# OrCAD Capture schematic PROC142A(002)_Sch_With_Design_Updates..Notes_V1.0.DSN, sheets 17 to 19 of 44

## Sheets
17 16. DDR4 INTERFACE: size C; title: DDR4 Interface
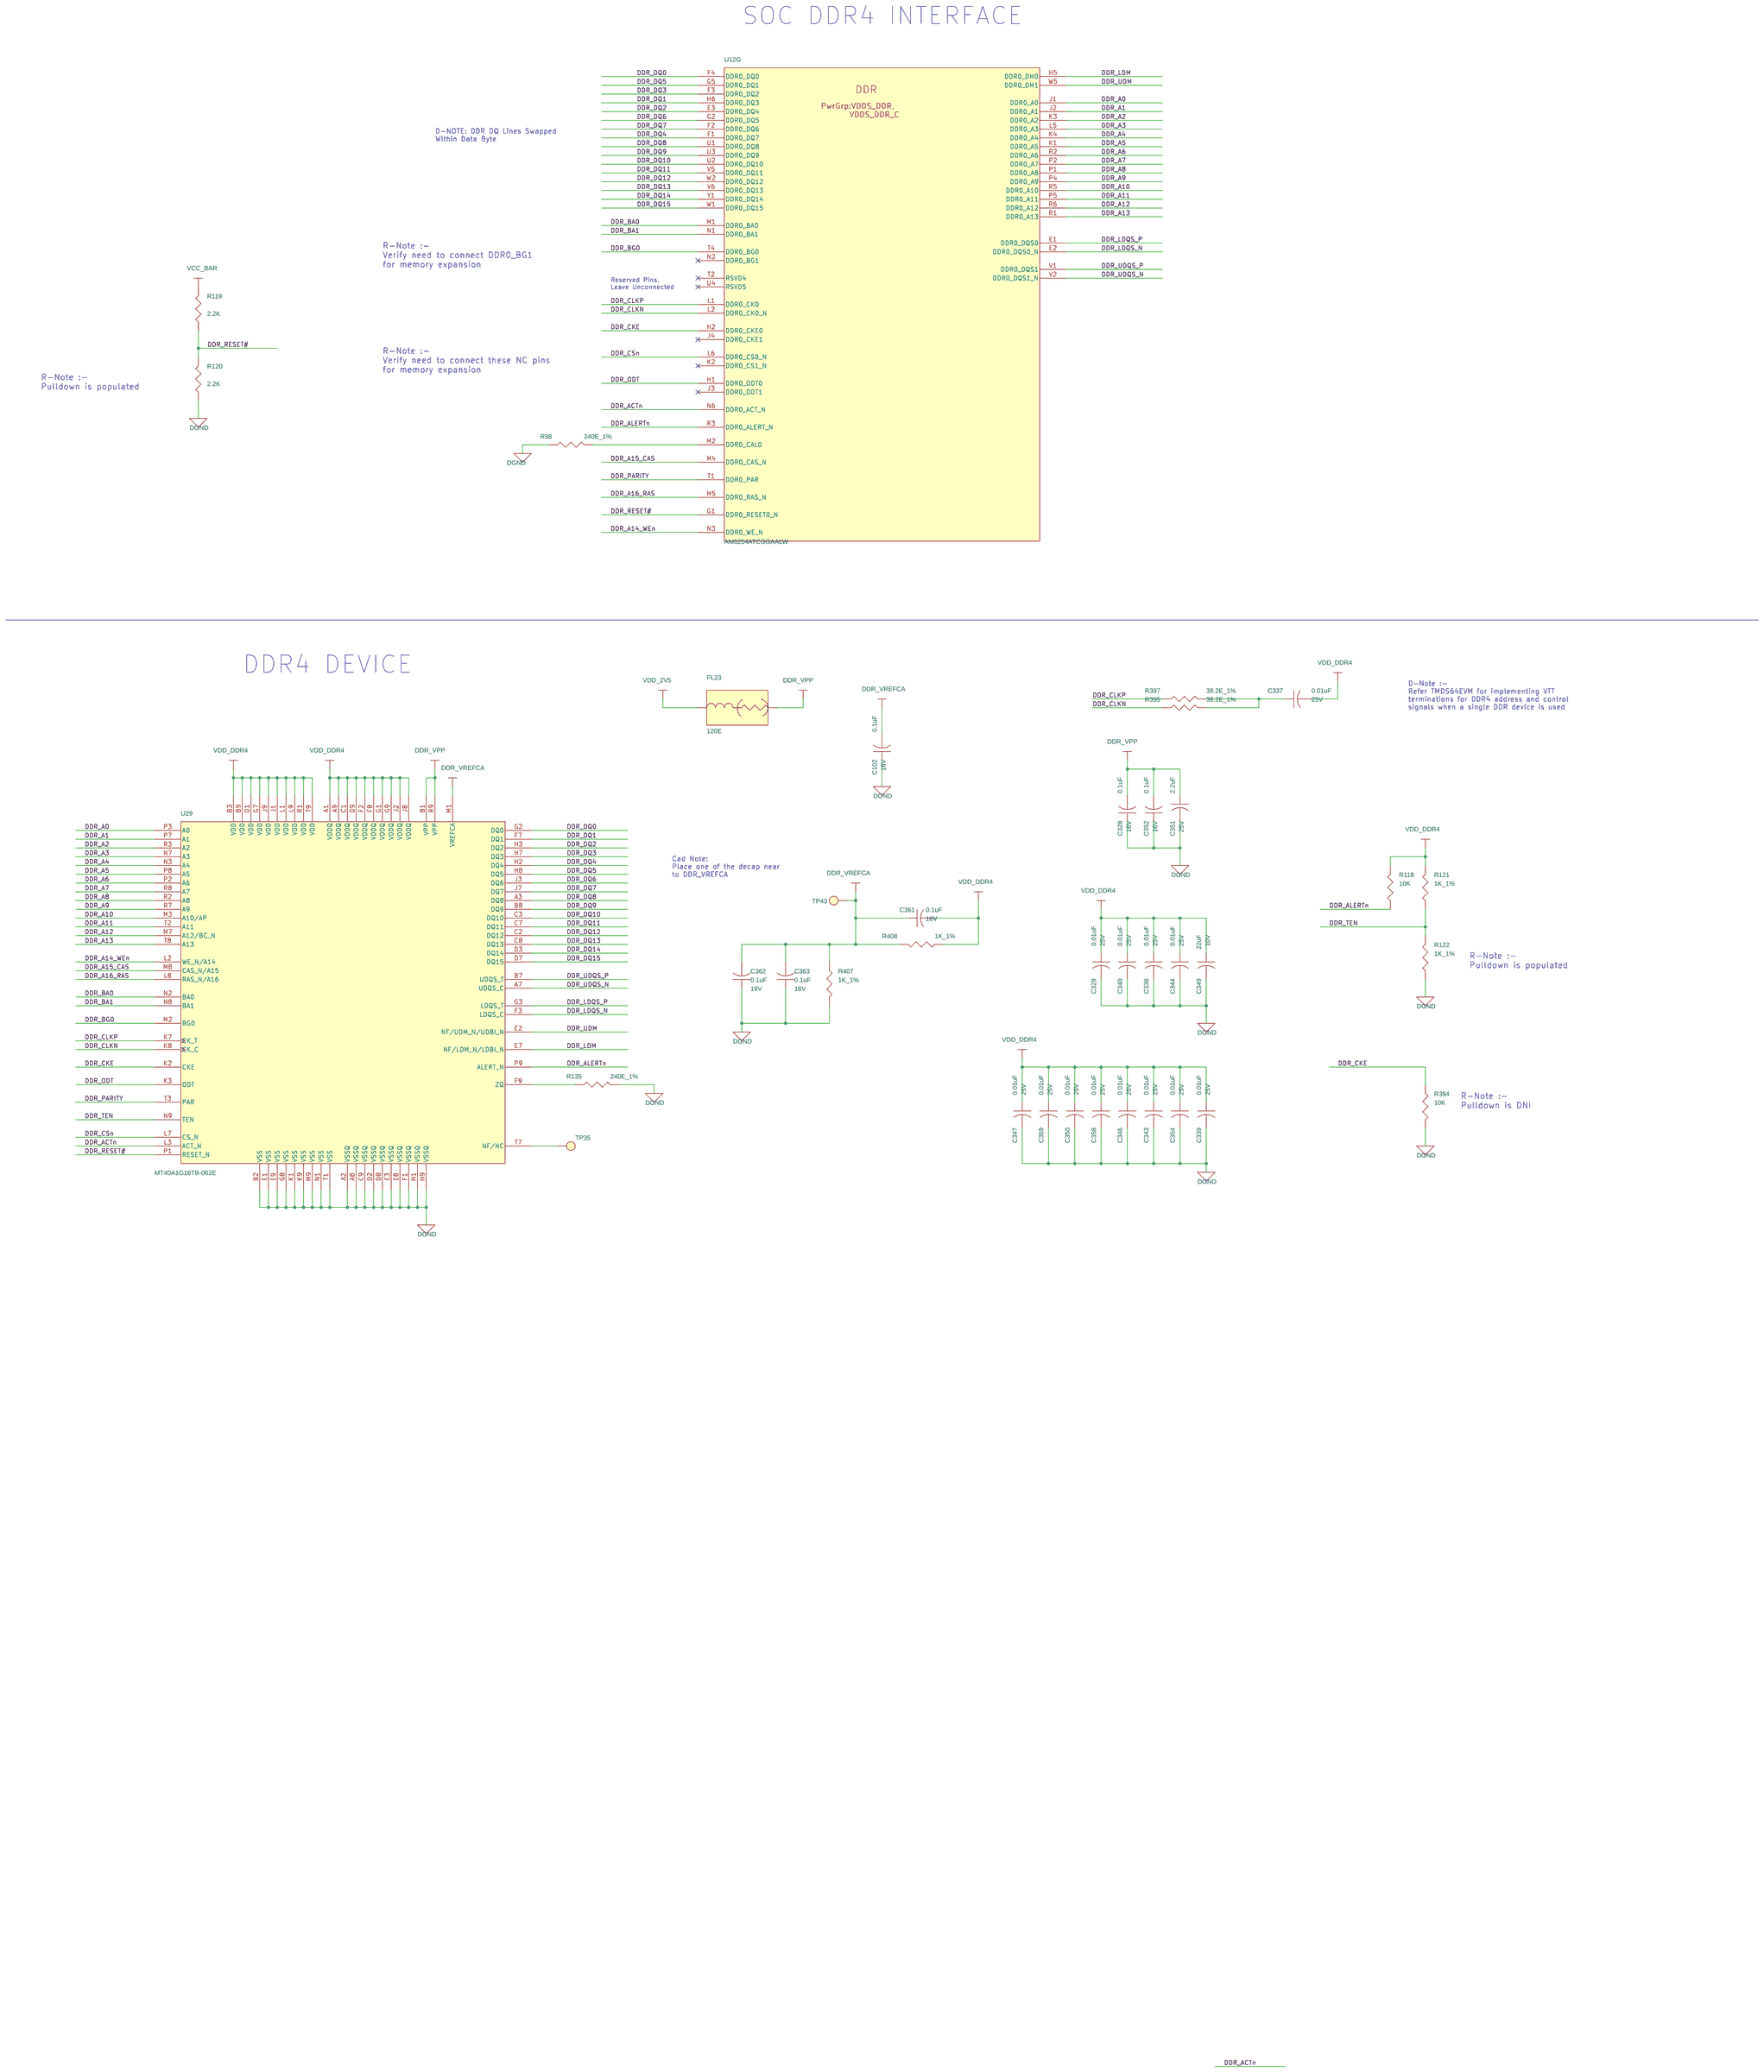
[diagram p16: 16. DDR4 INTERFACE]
18 17. M.2 INTERFACE: size C; title: M.2 CONNECTOR
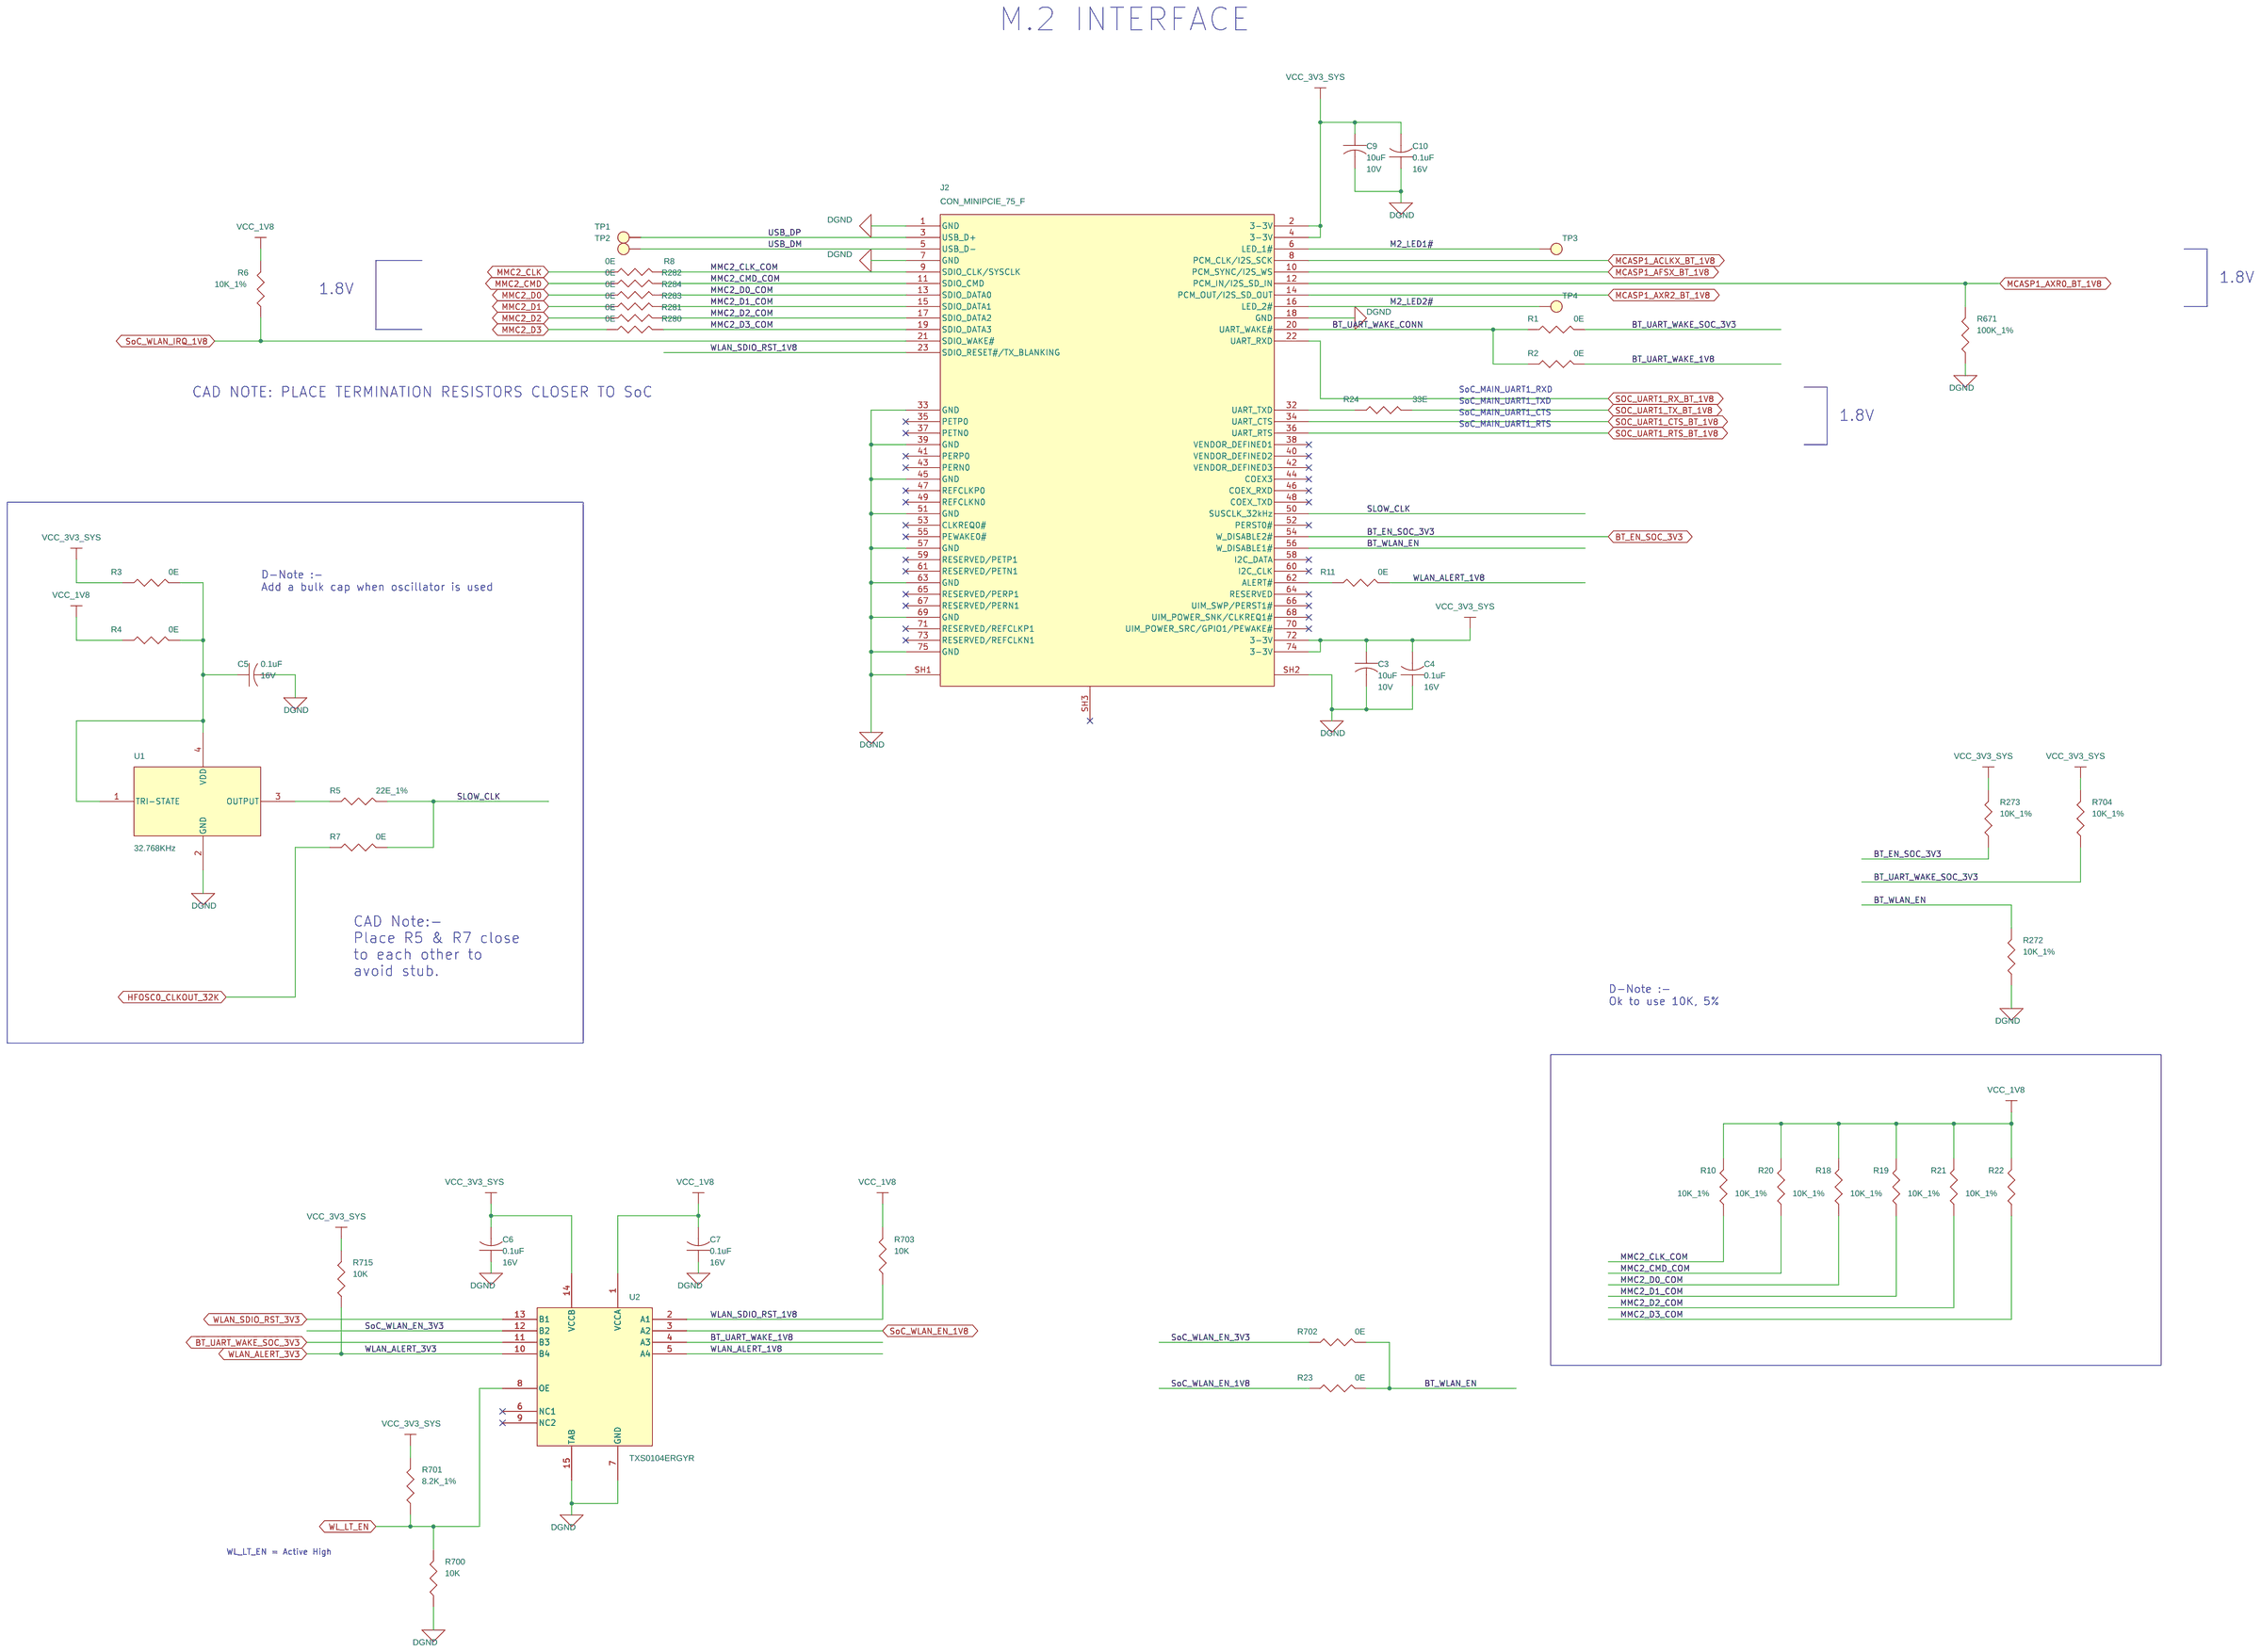
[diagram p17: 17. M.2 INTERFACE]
19 18. eMMC FLASH: size C; title: eMMC FLASH INTERFACE
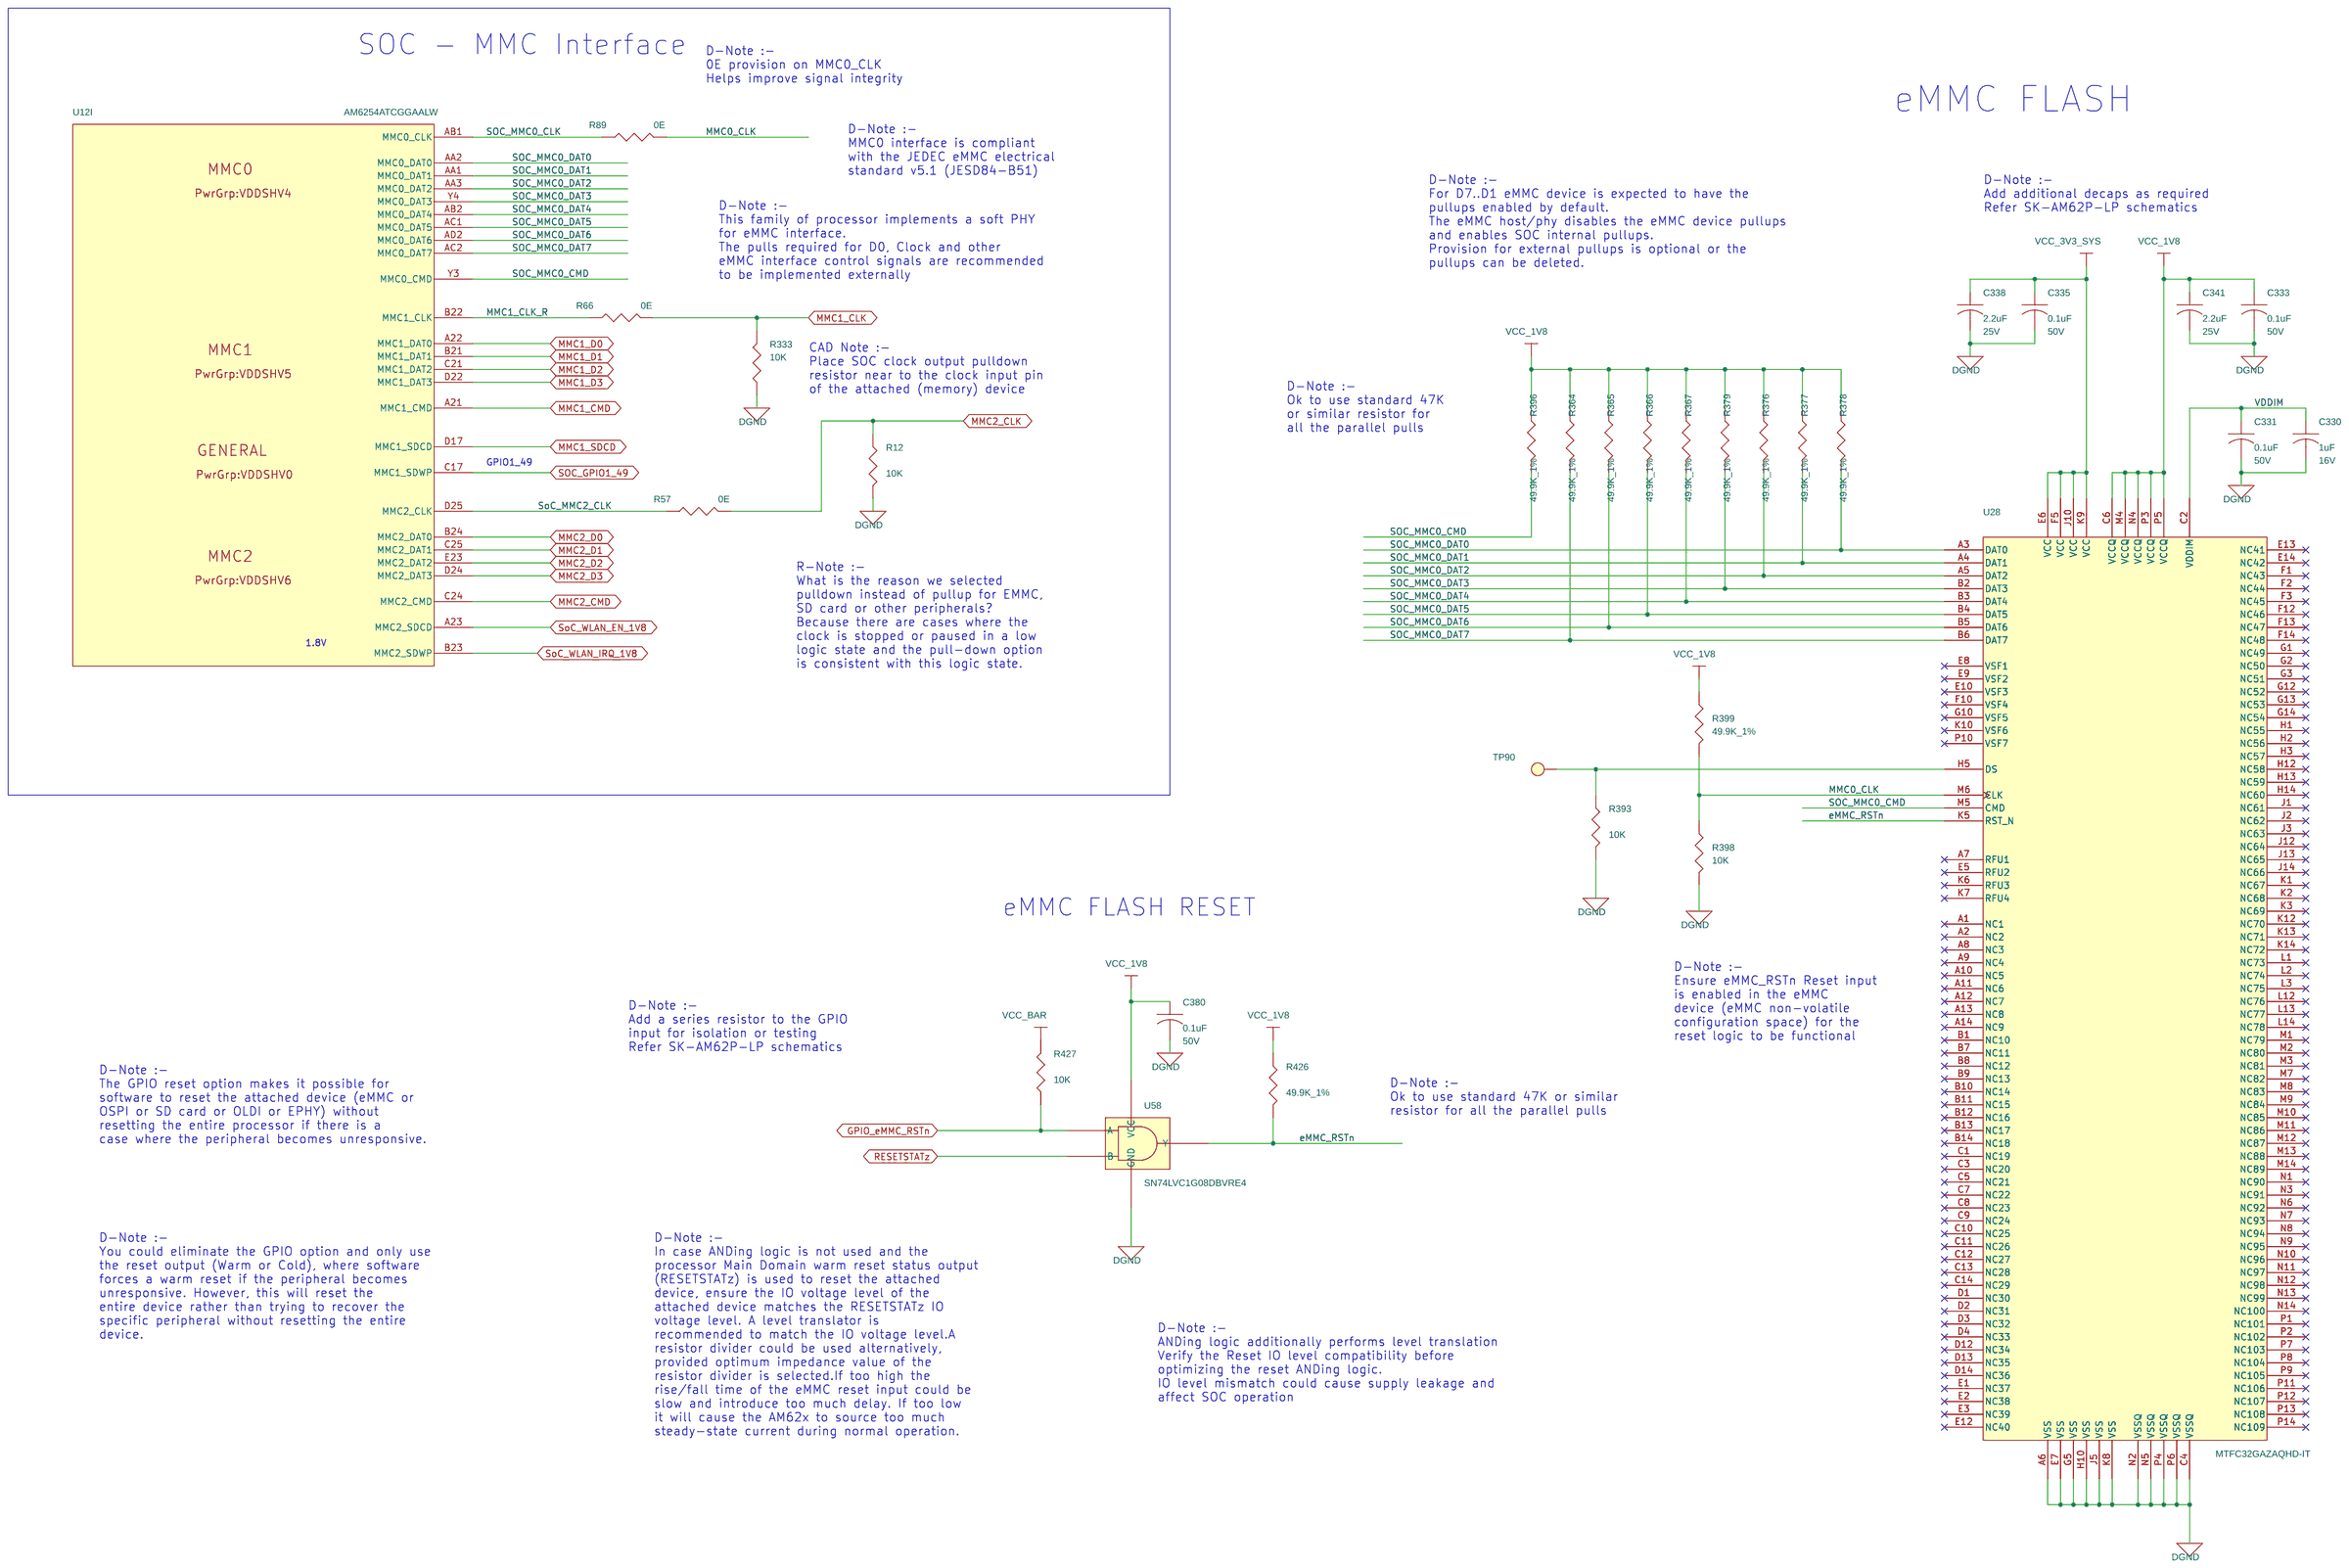
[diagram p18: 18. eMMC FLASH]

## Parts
sheet 16. DDR4 INTERFACE
C102  0.1uF  [CAP0201_0-5]
C328  0.1uF  [CAP0201_0-5]
C329  0.01uF  [CAP0201_0-5]
C336  0.01uF  [CAP0201_0-5]
C337  0.01uF  [CAP0201_0-5]
C339  0.01uF  [CAP0201_0-5]
C340  0.01uF  [CAP0201_0-5]
C343  0.01uF  [CAP0201_0-5]
C344  0.01uF  [CAP0201_0-5]
C346  0.01uF  [CAP0201_0-5]
C347  0.01uF  [CAP0201_0-5]
C349  22uF  [CAP0603_1]
C350  0.01uF  [CAP0201_0-5]
C351  2.2uF  [CAP0402_0-75]
C352  0.1uF  [CAP0201_0-5]
C354  0.01uF  [CAP0201_0-5]
C358  0.01uF  [CAP0201_0-5]
C359  0.01uF  [CAP0201_0-5]
C361  0.1uF  [CAP0201_0-5]
C362  0.1uF  [CAP0201_0-5]
C363  0.1uF  [CAP0201_0-5]
FL23  120E  [EMIFIL_BLM15A_0402_0-6]
R98  240E_1%  [RES0402_0-5]
R118  10K  [RES0201_0-5]
R119  2.2K  [RES0201_0-5]
R120  2.2K  [RES0402_0-5]
R121  1K_1%  [RES0402_0-5]
R122  1K_1%  [RES0402_0-5]
R135  240E_1%  [RES0402_0-5]
R394  10K  [RES0201_0-5]
R395  39.2E_1%  [RES0402_0-5]
R397  39.2E_1%  [RES0402_0-5]
R407  1K_1%  [RES0201_0-5]
R408  1K_1%  [RES0201_0-5]
TP35  TP20_SMD  [TP20_SMD]
TP43  TP20_SMD  [TP20_SMD]
U29  MT40A1G16TB-062E  [FBGA96_31-49_300X520_1-2]
sheet 17. M.2 INTERFACE
C3  10uF  [CAP0402_0-75]
C4  0.1uF  [CAP0201_0-5]
C5  0.1uF  [CAP0201_0-5]
C6  0.1uF  [CAP0201_0-5]
C7  0.1uF  [CAP0201_0-5]
C9  10uF  [CAP0402_0-75]
C10  0.1uF  [CAP0201_0-5]
J2  CON_MINIPCIE_75_F  [CON_MINIPCI75_2199119-4_S_R_S_3-2_2230]
R1  0E  [RES0201_0-5]
R2  0E  [RES0201_0-5]
R3  0E  [RES0201_0-5]
R4  0E  [RES0201_0-5]
R5  22E_1%  [RES0201_0-5]
R6  10K_1%  [RES0201_0-5]
R7  0E  [RES0201_0-5]
R8  0E  [RES0402_0-5]
R10  10K_1%  [RES0201_0-5]
R11  0E  [RES0201_0-5]
R18  10K_1%  [RES0201_0-5]
R19  10K_1%  [RES0201_0-5]
R20  10K_1%  [RES0201_0-5]
R21  10K_1%  [RES0201_0-5]
R22  10K_1%  [RES0201_0-5]
R23  0E  [RES0201_0-5]
R24  33E  [RES0201_0-5]
R272  10K_1%  [RES0201_0-5]
R273  10K_1%  [RES0201_0-5]
R280  0E  [RES0402_0-5]
R281  0E  [RES0402_0-5]
R282  0E  [RES0402_0-5]
R283  0E  [RES0402_0-5]
R284  0E  [RES0402_0-5]
R671  100K_1%  [RES0402_0-5]
R700  10K  [RES0201_0-5]
R701  8.2K_1%  [RES0201_0-5]
R702  0E  [RES0201_0-5]
R703  10K  [RES0201_0-5]
R704  10K_1%  [RES0201_0-5]
R715  10K  [RES0201_0-5]
TP1  TP20_SMD  [TP20_SMD]
TP2  TP20_SMD  [TP20_SMD]
TP3  TP20_SMD  [TP20_SMD]
TP4  TP20_SMD  [TP20_SMD]
U1  32.768KHz  [OSC4_ASDK_105X85_SMD]
U2  TXS0104ERGYR  [QFN14_19-68_145X145]
sheet 18. eMMC FLASH
C330  1uF  [CAP0201_0-5]
C331  0.1uF  [CAP0402_0-75]
C333  0.1uF  [CAP0402_0-75]
C335  0.1uF  [CAP0402_0-75]
C338  2.2uF  [CAP0402_0-75]
C341  2.2uF  [CAP0402_0-75]
C380  0.1uF  [CAP0402_0-75]
R12  10K  [RES0201_0-5]
R57  0E  [RES0201_0-5]
R66  0E  [RES0201_0-5]
R89  0E  [RES0201_0-5]
R333  10K  [RES0201_0-5]
R364  49.9K_1%  [RES0201_0-5]
R365  49.9K_1%  [RES0201_0-5]
R366  49.9K_1%  [RES0201_0-5]
R367  49.9K_1%  [RES0201_0-5]
R376  49.9K_1%  [RES0201_0-5]
R377  49.9K_1%  [RES0201_0-5]
R378  49.9K_1%  [RES0201_0-5]
R379  49.9K_1%  [RES0201_0-5]
R393  10K  [RES0201_0-5]
R396  49.9K_1%  [RES0201_0-5]
R398  10K  [RES0201_0-5]
R399  49.9K_1%  [RES0402_0-5]
R426  49.9K_1%  [RES0402_0-5]
R427  10K  [RES0201_0-5]
TP90  TP20_SMD  [TP20_SMD]
U28  MTFC32GAZAQHD-IT  [VFBGA153_19-68_460X520_0-9]
U58  SN74LVC1G08DBVRE4  [SOT23-5]
sheet 42. OSCILLATOR
U12  AM6254ATCGGAALW  [BGA425_19-68_510X510_0-7]  (sections A,B,C,D,E,F,G,H,I,J,K,L,M,N,O,P,Q,R)

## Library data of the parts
C102 C328 C352 = CAP: CAP CERAMIC 0.1uF 16V 10% X5R 0201; Chkd/date: MANIRAJA/230118; Crtd /date: MANIRAJA/230118; Custom_Duty: 15%; Customs_HS_Code: 85322990; Distributor_name: DIGIKEY; Distributor_part_number: 490-14305-1-ND; Footprint Path: Y:\MIS_DATABASE\Library\ALTIUM_TOOL\PCB_FOOTPRINTS\Altium_Footprint_Lib.PcbLib; Height: 0.33MM; Library Path: Y:\MIS_DATABASE\Library\ALTIUM_TOOL\SCHEMATICS_PARTS\MS_DISCRETE_Library.schlib; Mfr_name: MURATA; Mfr_part_number: GRM033R61C104KE14D; Mistral Part No: 120009030072-R; Package: 0201; Part_type: CAPACITORS\CERAMIC; Project: TI_MAXIE_CPB; RoHS: RoHS; Temperature: -55°C+85°C; Tolerance: 10%; Voltage: 16V; Wattage: NA; Weight: 0.33mg; Datasheet: Y:\MIS_DATABASE\DATASHEETS\CAPACITORS\GRM033R61C104KE14.PDF
C329 C336 C337 C339 C340 C343 C344 C346 C347 C350 C354 C358 C359 = CAP: CAP CERAMIC 0.01uF 25V 10% X5R 0201; Chkd/date: MANIRAJA/230118; Crtd /date: MANIRAJA/230118; Custom_Duty: 15%; Customs_HS_Code: 85322990; Distributor_name: DIGIKEY; Distributor_part_number: GRM033R61E103KA12J-ND; Footprint Path: Y:\MIS_DATABASE\Library\ALTIUM_TOOL\PCB_FOOTPRINTS\Altium_Footprint_Lib.PcbLib; Height: 0.33MM; Library Path: Y:\MIS_DATABASE\Library\ALTIUM_TOOL\SCHEMATICS_PARTS\MS_DISCRETE_Library.schlib; Mfr_name: MURATA; Mfr_part_number: GRM033R61E103KA12J; Mistral Part No: 120018010007-R; Package: 0201; Part_type: CAPACITORS\CERAMIC; Project: TI_MAXIE_CPB; RoHS: RoHS; Temperature: -55°C+85°C; Tolerance: 10%; Voltage: 25V; Wattage: NA; Weight: 0.33mg; Datasheet: Y:\MIS_DATABASE\DATASHEETS\CAPACITORS\GRM033R61E103KA12.PDF
C349 = CAP: CAP CERAMIC 22uF 10V 20% X5R 0603; Chkd/date: MANIRAJA/230118; Crtd /date: MANIRAJA/230118; Custom_Duty: 15%; Customs_HS_Code: 85322990; Distributor_name: DIGIKEY; Distributor_part_number: 490-10476-1-ND; Footprint Path: Y:\MIS_DATABASE\Library\ALTIUM_TOOL\PCB_FOOTPRINTS\Altium_Footprint_Lib.PcbLib; Height: 1.00MM; Library Path: Y:\MIS_DATABASE\Library\ALTIUM_TOOL\SCHEMATICS_PARTS\MS_DISCRETE_Library.schlib; Mfr_name: MURATA; Mfr_part_number: GRM188R61A226ME15D; Mistral Part No: 120014100009-R; Package: 0603; Part_type: CAPACITORS\CERAMIC; Project: TI_MAXIE_CPB; RoHS: RoHS; Temperature: -55°C+85°C; Tolerance: 20%; Voltage: 10V; Wattage: NA; Weight: 6.3mg; Datasheet: Y:\MIS_DATABASE\DATASHEETS\CAPACITORS\GRM188R61A226ME15.PDF
C338 C341 C351 = CAP: CAP CERAMIC 2.2uF 25V 10% X5R 0402; Chkd/date: ALVY/010721; Crtd /date: MANIRAJA/010721; Custom_Duty: 15%; Customs_HS_Code: 85322990; Distributor_name: DIGIKEY; Distributor_part_number: 490-12703-1-ND; Footprint Path: Y:\MIS_DATABASE\Library\ALTIUM_TOOL\PCB_FOOTPRINTS\Altium_Footprint_Lib.PcbLib; Height: 0.70MM; Library Path: Y:\MIS_DATABASE\Library\ALTIUM_TOOL\SCHEMATICS_PARTS\MS_DISCRETE_Library.schlib; Mfr_name: MURATA; Mfr_part_number: GRM155R61E225KE11D; Mistral Part No: 120015120001-R; Package: 0402; Part_type: CAPACITORS\CERAMIC; Project: TI_AM263X_CC; RoHS: RoHS; Temperature: -55°C+85°C; Tolerance: 10%; Voltage: 25V; Wattage: NA; Weight: 1.5mg; Datasheet: Y:\MIS_DATABASE\DATASHEETS\CAPACITORS\GRM155R61E225KE11.PDF
C4-C7 C10 C361-C363 = CAP: CAP CERAMIC 0.1uF 16V 10% X5R 0201; Alt_Mfr_name: YAGEO AMERICA; Alt_Mfr_part_number: CC0402KRX5R8BB104; Chkd/date: MANIRAJA/230118; Crtd /date: MANIRAJA/230118; Custom_Duty: 15%; Customs_HS_Code: 85322990; Distributor_name: DIGIKEY; Distributor_part_number: 490-14305-1-ND; Footprint Path: Y:\MIS_DATABASE\Library\ALTIUM_TOOL\PCB_FOOTPRINTS\Altium_Footprint_Lib.PcbLib; Height: 0.33MM; Library Path: Y:\MIS_DATABASE\Library\ALTIUM_TOOL\SCHEMATICS_PARTS\MS_DISCRETE_Library.schlib; Mfr_name: MURATA; Mfr_part_number: GRM033R61C104KE14D; Mistral Part No: 120009030072-R; Package: 0201; Part_type: CAPACITORS\CERAMIC; Project: TI_MAXIE_CPB; RoHS: RoHS; Temperature: -55°C+85°C; Tolerance: 10%; Voltage: 16V; Wattage: NA; Weight: 0.33mg; Datasheet: Y:\MIS_DATABASE\DATASHEETS\CAPACITORS\GRM033R61C104KE14.PDF
FL23 = EMIFILTER_IND: IND FERRITE BEAD CHIP 120E 2A 0402; Chkd/date: NAVEED/241114; Crtd /date: USMAN/170613; Custom_Duty: 24%; Customs_HS_Code: 85369090; Distributor_name: DIGIKEY; Distributor_part_number: 490-9656-1-ND; Footprint Path: Y:\MIS_DATABASE\Library\ALTIUM_TOOL\PCB_FOOTPRINTS\Altium_Footprint_Lib.PcbLib; Height: 0.55MM; Library Path: Y:\MIS_DATABASE\Library\ALTIUM_TOOL\SCHEMATICS_PARTS\MS_FILTER_Library.schlib; Mfr_name: MURATA; Mfr_part_number: BLM15PX121SN1D; Mistral Part No: 130013060022-R; Package: 0402; Part_type: INDUCTOR; Project: GEN_3-8; RoHS: RoHS; Temperature: -55°C+125°C; Tolerance: 25%; Voltage: NA; Wattage: NA; Weight: 1mg; Datasheet: Y:\MIS_DATABASE\DATASHEETS\DISCRETES\INDUCTORS\BLM15-SN1-SER.PDF
R98 R135 = RESISTOR: RES 240E 1/10W 1% 0402; Chkd/date: MAZHAR/150611; Crtd /date: BAVISH/020611; Custom_Duty: 15%; Customs_HS_Code: 85332119; Distributor_name: DIGIKEY; Distributor_part_number: P240LCT-ND; Footprint Path: Y:\MIS_DATABASE\Library\ALTIUM_TOOL\PCB_FOOTPRINTS\Altium_Footprint_Lib.PcbLib; Height: 0.40MM; Library Path: Y:\MIS_DATABASE\Library\ALTIUM_TOOL\SCHEMATICS_PARTS\MS_DISCRETE_Library.schlib; Mfr_name: PANASONIC-ECG; Mfr_part_number: ERJ-2RKF2400X; Mistral Part No: 110011060017-R; Package: 0402; Part_type: RESISTORS\FIXED; Project: AM4515_EVM_LCD; RoHS: RoHS; Temperature: -55°C+155°C; Tolerance: 1%; Voltage: NA; Wattage: 1/10W; Weight: 0.8mg; Datasheet: Y:\MIS_DATABASE\DATASHEETS\RESISTORS\PAN-ERJSER_NOV17.PDF
R12 R118 R333 R393 R394 R398 R427 R700 R703 R715 = RESISTOR: RES 10K 1/20W 5% 0201; Chkd/date: MANIRAJA/050517; Crtd /date: MANIRAJA/050517; Custom_Duty: 15%; Customs_HS_Code: 85332119; Distributor_name: DIGIKEY; Distributor_part_number: 311-10KNCT-ND; Footprint Path: Y:\MIS_DATABASE\Library\ALTIUM_TOOL\PCB_FOOTPRINTS\Altium_Footprint_Lib.PcbLib; Height: 0.26MM; Library Path: Y:\MIS_DATABASE\Library\ALTIUM_TOOL\SCHEMATICS_PARTS\MS_DISCRETE_Library.schlib; Mfr_name: YAGEO AMERICA; Mfr_part_number: RC0201JR-0710KL; Mistral Part No: 110010070051-R; Package: 0201; Part_type: RESISTORS\FIXED; Project: GOLDEN-I LITE; RoHS: RoHS; Temperature: -55°C+125°C; Tolerance: 5%; Voltage: NA; Wattage: 1/20W; Weight: 0.17mg; Datasheet: Y:\MIS_DATABASE\DATASHEETS\RESISTORS\RCXXXXL-SER_MAR18.PDF
R119 = RESISTOR: RES 2.2K 1/20W 5% 0201; Chkd/date: VASANTHA/010117; Crtd /date: MAZHAR/010605; Custom_Duty: 15%; Customs_HS_Code: 85332119; Distributor_name: DIGIKEY; Distributor_part_number: P2.2KAGCT-ND; Footprint Path: Y:\MIS_DATABASE\Library\ALTIUM_TOOL\PCB_FOOTPRINTS\Altium_Footprint_Lib.PcbLib; Height: 0.26MM; Library Path: Y:\MIS_DATABASE\Library\ALTIUM_TOOL\SCHEMATICS_PARTS\MS_DISCRETE_Library.schlib; Mfr_name: PANASONIC-ECG; Mfr_part_number: ERJ-1GEJ222C; Mistral Part No: 110009030427-R; Package: 0201; Part_type: RESISTORS\FIXED; Project: G4SLIM; RoHS: RoHS; Temperature: -55°C+125°C; Tolerance: 5%; Voltage: NA; Wattage: 1/20W; Weight: 0.15mg; Datasheet: Y:\MIS_DATABASE\DATASHEETS\RESISTORS\PAN-ERJXGE-FEB06.PDF
R120 = RESISTOR: RES 2.2K 1/16W 5% 0402; Chkd/date: VASANTHA/061216; Crtd /date: BAVISH/021210; Custom_Duty: 15%; Customs_HS_Code: 85332119; Distributor_name: DIGIKEY; Distributor_part_number: 311-2.2KJRCT-ND; Footprint Path: Y:\MIS_DATABASE\Library\ALTIUM_TOOL\PCB_FOOTPRINTS\Altium_Footprint_Lib.PcbLib; Height: 0.40MM; Library Path: Y:\MIS_DATABASE\Library\ALTIUM_TOOL\SCHEMATICS_PARTS\MS_DISCRETE_Library.schlib; Mfr_name: YAGEO AMERICA; Mfr_part_number: RC0402JR-072K2L; Mistral Part No: 110010120018-R; Package: 0402; Part_type: RESISTORS\FIXED; Project: TE4; RoHS: RoHS; Temperature: -55°C+155°C; Tolerance: 5%; Voltage: NA; Wattage: 1/16W; Weight: 0.65mg; Datasheet: Y:\MIS_DATABASE\DATASHEETS\RESISTORS\RCXXXXL-SER_MAR18.PDF
R121 R122 = RESISTOR: RES 1K 1/10W 1% 0402; Chkd/date: VASANTHA/281216; Crtd /date: MAZHAR/150506; Custom_Duty: 15%; Customs_HS_Code: 85332119; Distributor_name: DIGIKEY; Distributor_part_number: P1.00KLCT-ND; Footprint Path: Y:\MIS_DATABASE\Library\ALTIUM_TOOL\PCB_FOOTPRINTS\Altium_Footprint_Lib.PcbLib; Height: 0.40MM; Library Path: Y:\MIS_DATABASE\Library\ALTIUM_TOOL\SCHEMATICS_PARTS\MS_DISCRETE_Library.schlib; Mfr_name: PANASONIC-ECG; Mfr_part_number: ERJ-2RKF1001X; Mistral Part No: 110009030411-R; Package: 0402; Part_type: RESISTORS\FIXED; Project: VOCERA; RoHS: RoHS; Temperature: -55°C+155°C; Tolerance: 1%; Voltage: NA; Wattage: 1/10W; Weight: 0.8mg; Datasheet: Y:\MIS_DATABASE\DATASHEETS\RESISTORS\PAN-ERJSER_NOV17.PDF
R395 R397 = RESISTOR: RES 39.2E 1/16W 1% 0402; Chkd/date: RAGESH/210411; Crtd /date: MAZHAR/210411; Custom_Duty: 15%; Customs_HS_Code: 85332119; Distributor_name: DIGIKEY; Distributor_part_number: RMCF0402FT39R2CT-ND; Footprint Path: Y:\MIS_DATABASE\Library\ALTIUM_TOOL\PCB_FOOTPRINTS\Altium_Footprint_Lib.PcbLib; Height: 0.40MM; Library Path: Y:\MIS_DATABASE\Library\ALTIUM_TOOL\SCHEMATICS_PARTS\MS_DISCRETE_Library.schlib; Mfr_name: STACKPOLE ELECTRONICS; Mfr_part_number: RMCF0402FT39R2; Mistral Part No: 110011040030-R; Package: 0402; Part_type: RESISTORS\FIXED; Project: AOD_POD-BASECARD; RoHS: RoHS; Temperature: -55°C+155°C; Tolerance: 1%; Voltage: NA; Wattage: 1/16W; Weight: 0.57mg; Datasheet: Y:\MIS_DATABASE\DATASHEETS\RESISTORS\RMCF-SER_JUL18.PDF
R407 R408 = RESISTOR: RES 1K 1/20W 1% 0201; Chkd/date: PRAVEEN/110822; Crtd /date: PRAVEEN/110822; Custom_Duty: 15%; Customs_HS_Code: 85332119; Distributor_name: DIGIKEY; Distributor_part_number: P122413CT-ND; Footprint Path: Y:\MIS_DATABASE\Library\ALTIUM_TOOL\PCB_FOOTPRINTS\Altium_Footprint_Lib.PcbLib; Height: 0.26MM; Library Path: Y:\MIS_DATABASE\Library\ALTIUM_TOOL\SCHEMATICS_PARTS\MS_DISCRETE_Library.schlib; Mfr_name: PANASONIC-ECG; Mfr_part_number: ERJ-1GNF1001C; Mistral Part No: 110022080039-R; Package: 0201; Part_type: RESISTORS\FIXED; Project: QCS6490 SOM_BRD; RoHS: RoHS; Temperature: -55°C+125°C; Tolerance: 1%; Voltage: NA; Wattage: 1/20W; Weight: 0.15mg; Datasheet: Y:\MIS_DATABASE\DATASHEETS\RESISTORS\PAN-ERJSER_NOV17.PDF
TP1-TP4 TP35 TP43 TP90 = TESTPOINT: TESTPOINT CIR 20 SMD; Chkd/date: SHREESHAIL/171006; Crtd /date: MAZHAR/171006; Custom_Duty: NA; Customs_HS_Code: NA; Distributor_name: NA; Distributor_part_number: NA; Footprint Path: Y:\MIS_DATABASE\Library\ALTIUM_TOOL\PCB_FOOTPRINTS\Altium_Footprint_Lib.PcbLib; Height: NA; Library Path: Y:\MIS_DATABASE\Library\ALTIUM_TOOL\SCHEMATICS_PARTS\MS_DISCRETE_Library.schlib; MECHANICAL 3D STEP FILE: NA; Mfr_name: LOCAL; Mistral Part No: NA; Package: SMD; Project: BT MODULE_CSRBC04; RoHS: NA; Temperature: NA; Tolerance: NA; Voltage: NA; Wattage: NA; Weight: NA; Datasheet: NA
U29 = MT40A512M16LY_FBGA96: IC 16Gb DDR4 SDRAM FBGA96; Chkd/date: PRAVEEN/031122; Crtd /date: PRAVEEN/031122; Custom_Duty: 15%; Customs_HS_Code: 85423100; Distributor_name: DIGIKEY; Distributor_part_number: 557-MT40A1G16TB-062EIT:F-ND; Footprint Path: Y:\MIS_DATABASE\Library\ALTIUM_TOOL\PCB_FOOTPRINTS\Altium_Footprint_Lib.PcbLib; Height: 1.20MM; Library Path: Y:\MIS_DATABASE\Library\ALTIUM_TOOL\SCHEMATICS_PARTS\MS_MISCMEMORY_Library.schlib; Mfr_name: MICRON; Mfr_part_number: MT40A1G16TB-062E IT:F; Mistral Part No: 141022110006-R; Package: FBGA96; Part_type: ICS\DIGITAL\MEMORY; Project: AM64x_SK_BRD; RoHS: RoHS; Temperature: -40°C+95°C; Tolerance: NA; Voltage: NA; Wattage: NA; Weight: NA; Datasheet: Y:\MIS_DATABASE\DATASHEETS\ICS\MEMORY\MT40A-SER.PDF
C3 C9 = CAP: CAP CERAMIC 10uF 10V 20% X5R 0402; Chkd/date: MANIRAJA/300520; Crtd /date: ALVY/260520; Custom_Duty: 15%; Customs_HS_Code: 85322990; Distributor_name: DIGIKEY; Distributor_part_number: 490-GRM155R61A106ME11DTR-ND; Footprint Path: Y:\MIS_DATABASE\Library\ALTIUM_TOOL\PCB_FOOTPRINTS\Altium_Footprint_Lib.PcbLib; Height: 0.55MM; Library Path: Y:\MIS_DATABASE\Library\ALTIUM_TOOL\SCHEMATICS_PARTS\MS_DISCRETE_Library.schlib; Mfr_name: MURATA; Mfr_part_number: GRM155R61A106ME11D; Mistral Part No: 120013110019-R; Package: 0402; Part_type: CAPACITORS\CERAMIC; Project: QCS610_NANOSOM; RoHS: RoHS; Temperature: -55°C+85°C; Tolerance: 20%; Voltage: 10V; Wattage: NA; Weight: 3.1mg; Datasheet: Y:\MIS_DATABASE\DATASHEETS\CAPACITORS\MURATA-GXX-SER_NOV17.PDF
J2 = CON_PCI_75_2199119-4_2230: CON MINIPCI 75POS 0.50MM PITCH FEMALE RT SMD; Chkd/date: ALVY/300521; Crtd /date: ALVY/300521; Custom_Duty: 24%; Customs_HS_Code: 85369090; Distributor_name: DIGIKEY; Distributor_part_number: A115900CT-ND; Footprint Path: Y:\MIS_DATABASE\Library\ALTIUM_TOOL\PCB_FOOTPRINTS\Altium_Footprint_Lib.PcbLib; Height: 3.20MM; Library Path: Y:\MIS_DATABASE\Library\ALTIUM_TOOL\SCHEMATICS_PARTS\MS_CONNECTOR_Library.schlib; Mfr_name: TE CONNECTIVITY; Mfr_part_number: 2199119-4_2230; Mistral Part No: 150021030016-R; Package: SMD; Part_type: CONNECTOR\PCI; Project: VOLTA_CHARGER V5; RoHS: RoHS; Temperature: -40°C+80°C; Tolerance: NA; Voltage: NA; Wattage: NA; Weight: 506mg; Datasheet: Y:\MIS_DATABASE\DATASHEETS\CONNECTORS\2199119.PDF
R1-R4 R7 R11 R23 R702 = RESISTOR: RES 0E 1/20W 5% 0201; Chkd/date: NAVEED/301214; Crtd /date: MUDDU/120710; Custom_Duty: 15%; Customs_HS_Code: 85332119; Distributor_name: DIGIKEY; Distributor_part_number: 311-0.0NCT-ND; Footprint Path: Y:\MIS_DATABASE\Library\ALTIUM_TOOL\PCB_FOOTPRINTS\Altium_Footprint_Lib.PcbLib; Height: 0.26MM; Library Path: Y:\MIS_DATABASE\Library\ALTIUM_TOOL\SCHEMATICS_PARTS\MS_DISCRETE_Library.schlib; Mfr_name: YAGEO AMERICA; Mfr_part_number: RC0201JR-070RL; Mistral Part No: 110010070067-R; Package: 0201; Part_type: RESISTORS\FIXED; Project: PB_BUGBASE; RoHS: RoHS; Temperature: -55°C+125°C; Tolerance: 5%; Voltage: NA; Wattage: 1/20W; Weight: 0.17mg; Datasheet: Y:\MIS_DATABASE\DATASHEETS\RESISTORS\RCXXXXL-SER_MAR18.PDF
R5 = RESISTOR: RES 22E 1/20W 1% 0201; Chkd/date: MAZHAR/140709; Crtd /date: MAZHAR/220807; Custom_Duty: 15%; Customs_HS_Code: 85332119; Distributor_name: DIGIKEY; Distributor_part_number: P22.0ABCT-ND; Footprint Path: Y:\MIS_DATABASE\Library\ALTIUM_TOOL\PCB_FOOTPRINTS\Altium_Footprint_Lib.PcbLib; Height: 0.26MM; Library Path: Y:\MIS_DATABASE\Library\ALTIUM_TOOL\SCHEMATICS_PARTS\MS_DISCRETE_Library.schlib; Mfr_name: PANASONIC-ECG; Mfr_part_number: ERJ-1GEF22R0C; Mistral Part No: 110009030522-R; Package: 0201; Part_type: RESISTORS\FIXED; Project: V8TS; RoHS: RoHS; Temperature: -55°C+125°C; Tolerance: 1%; Voltage: NA; Wattage: 1/20W; Weight: 0.15mg; Datasheet: Y:\MIS_DATABASE\DATASHEETS\RESISTORS\PAN-ERJSER_NOV17.PDF
R6 R10 R18-R22 R272 R273 R704 = RESISTOR: RES 10K 1/20W 1% 0201; Chkd/date: VASANTHA/270117; Crtd /date: MANIRAJA/270117; Custom_Duty: 15%; Customs_HS_Code: 85332119; Distributor_name: DIGIKEY; Distributor_part_number: 311-10.0KMCT-ND; Footprint Path: Y:\MIS_DATABASE\Library\ALTIUM_TOOL\PCB_FOOTPRINTS\Altium_Footprint_Lib.PcbLib; Height: 0.26MM; Library Path: Y:\MIS_DATABASE\Library\ALTIUM_TOOL\SCHEMATICS_PARTS\MS_DISCRETE_Library.schlib; Mfr_name: YAGEO AMERICA; Mfr_part_number: RC0201FR-0710KL; Mistral Part No: 110011040018-R; Package: 0201; Part_type: RESISTORS\FIXED; Project: GOLDEN-I LITE; RoHS: RoHS; Temperature: -55°C+125°C; Tolerance: 1%; Voltage: NA; Wattage: 1/20W; Weight: 0.17mg; Datasheet: Y:\MIS_DATABASE\DATASHEETS\RESISTORS\RCXXXXL-SER_MAR18.PDF
R8 R280-R284 = RESISTOR: RES 0E 1/16W JUMPER 0402; Chkd/date: VASANTHA/201216; Crtd /date: MUDDU/190810; Custom_Duty: 15%; Customs_HS_Code: 85332119; Distributor_name: DIGIKEY; Distributor_part_number: 541-0.0JCT-ND; Footprint Path: Y:\MIS_DATABASE\Library\ALTIUM_TOOL\PCB_FOOTPRINTS\Altium_Footprint_Lib.PcbLib; Height: 0.40MM; Library Path: Y:\MIS_DATABASE\Library\ALTIUM_TOOL\SCHEMATICS_PARTS\MS_DISCRETE_Library.schlib; Mfr_name: VISHAY; Mfr_part_number: CRCW04020000Z0ED; Mistral Part No: 110010080019-R; Package: 0402; Part_type: RESISTORS\FIXED; Project: PB_BUGBASE; RoHS: RoHS; Temperature: -55°C+155°C; Tolerance: NA; Voltage: NA; Wattage: 1/16W; Weight: 0.65mg; Datasheet: Y:\MIS_DATABASE\DATASHEETS\RESISTORS\CRCW0603.PDF
R24 = RESISTOR: RES 33E 1/20W 5% 0201; Chkd/date: VASANTHA/061216; Crtd /date: MAZHAR/170505; Custom_Duty: 15%; Customs_HS_Code: 85332119; Distributor_name: DIGIKEY; Distributor_part_number: P33AGCT-ND; Footprint Path: Y:\MIS_DATABASE\Library\ALTIUM_TOOL\PCB_FOOTPRINTS\Altium_Footprint_Lib.PcbLib; Height: 0.26MM; Library Path: Y:\MIS_DATABASE\Library\ALTIUM_TOOL\SCHEMATICS_PARTS\MS_DISCRETE_Library.schlib; Mfr_name: PANASONIC-ECG; Mfr_part_number: ERJ-1GEJ330C; Mistral Part No: 110010070052-R; Package: 0201; Part_type: RESISTORS\FIXED; Project: G4SLIM; RoHS: RoHS; Temperature: -55°C+125°C; Tolerance: 5%; Voltage: NA; Wattage: 1/20W; Weight: 0.15mg; Datasheet: Y:\MIS_DATABASE\DATASHEETS\RESISTORS\PAN-ERJXGE-FEB06.PDF
R671 = RESISTOR: RES 100K 1/10W 1% 0402; Chkd/date: VASANTHA/201216; Crtd /date: MAZHAR/130306; Custom_Duty: 15%; Customs_HS_Code: 85332119; Distributor_name: DIGIKEY; Distributor_part_number: P100KLCT-ND; Footprint Path: Y:\MIS_DATABASE\Library\ALTIUM_TOOL\PCB_FOOTPRINTS\Altium_Footprint_Lib.PcbLib; Height: 0.40MM; Library Path: Y:\MIS_DATABASE\Library\ALTIUM_TOOL\SCHEMATICS_PARTS\MS_DISCRETE_Library.schlib; Mfr_name: PANASONIC-ECG; Mfr_part_number: ERJ-2RKF1003X; Mistral Part No: 110009030187-R; Package: 0402; Part_type: RESISTORS\FIXED; Project: J32; RoHS: RoHS; Temperature: -55°C+155°C; Tolerance: 1%; Voltage: NA; Wattage: 1/10W; Weight: 0.8mg; Datasheet: Y:\MIS_DATABASE\DATASHEETS\RESISTORS\PAN-ERJSER_NOV17.PDF
R701 = RESISTOR: RES 8.2K 1/20W 1% 0201; Chkd/date: SUHAS/230910; Crtd /date: MUDDU/060710; Custom_Duty: 15%; Customs_HS_Code: 85332119; Distributor_name: DIGIKEY; Distributor_part_number: 541-8.20KAABCT-ND; Footprint Path: Y:\MIS_DATABASE\Library\ALTIUM_TOOL\PCB_FOOTPRINTS\Altium_Footprint_Lib.PcbLib; Height: 0.28MM; Library Path: Y:\MIS_DATABASE\Library\ALTIUM_TOOL\SCHEMATICS_PARTS\MS_DISCRETE_Library.schlib; Mfr_name: VISHAY; Mfr_part_number: CRCW02018K20FKED; Mistral Part No: 110010070001-R; Package: 0201; Part_type: RESISTORS\FIXED; Project: PB_BUGBASE; RoHS: RoHS; Temperature: -55°C+155°C; Tolerance: 1%; Voltage: NA; Wattage: 1/20W; Weight: 0.17mg; Datasheet: Y:\MIS_DATABASE\DATASHEETS\RESISTORS\CRCW0201.PDF
U1 = OSC4_ASFL3: OSC 32.768KHz 1.8V SMD; Chkd/date: SUHAS/100710; Crtd /date: USMAN/020409; Custom_Duty: 24%; Customs_HS_Code: 85437099; Distributor_name: DIGIKEY; Distributor_part_number: 535-10003-1-ND; Height: 0.95MM; Mfr_name: ABRACON; Mfr_part_number: ASDK2-32.768KHZ-LRT; Mistral Part No: 130009031113-R; Package: SMD; Part_type: OSCILLATORS; Project: AXON; RoHS: RoHS; Temperature: -40°C+85°C; Voltage: 1.8V; Weight: NA; Datasheet: Y:\MIS_DATABASE\DATASHEETS\MISC\CRY_OSC\ASDK.PDF
U2 = TXS0104ERGYR_QFN14: IC 4-BIT BIDIRECTIONAL VOLTAGE-LEVEL TRANSLATOR QFN14; Chkd/date: SHREESHAIL/170108; Crtd /date: SHREESHAIL/170108; Custom_Duty: 15%; Customs_HS_Code: 85423100; Distributor_name: DIGIKEY; Distributor_part_number: 296-20698-1-ND; Height: 1.00MM; Mfr_name: TEXAS INSTRUMENTS; Mistral Part No: 141009030362-R; Package: QFN14; Part_type: ICS\INTERFACE; Project: HS100RD; RoHS: Sb/ Br FREE; Datasheet: Y:\MIS_DATABASE\DATASHEETS\ICS\INTERFACE\TXS0104E.PDF
C330 = CAP: CAP CERAMIC 1uF 16V 20% X5R 0201; Chkd/date: MANIRAJA/300520; Crtd /date: ALVY/260520; Custom_Duty: 15%; Customs_HS_Code: 85322990; Distributor_name: DIGIKEY; Distributor_part_number: 490-18654-1-ND; Footprint Path: Y:\MIS_DATABASE\Library\ALTIUM_TOOL\PCB_FOOTPRINTS\Altium_Footprint_Lib.PcbLib; Height: 0.39MM; Library Path: Y:\MIS_DATABASE\Library\ALTIUM_TOOL\SCHEMATICS_PARTS\MS_DISCRETE_Library.schlib; Mfr_name: MURATA; Mfr_part_number: GRM033R61C105ME15D; Mistral Part No: 120018090038-R; Package: 0201; Part_type: CAPACITORS\CERAMIC; Project: QCS610_NANOSOM; RoHS: RoHS; Temperature: -55°C+85°C; Tolerance: 20%; Voltage: 16V; Wattage: NA; Weight: 0.33mg; Datasheet: Y:\MIS_DATABASE\DATASHEETS\CAPACITORS\GRM033R61C105ME15.PDF
C331 C333 C335 C380 = CAP: CAP CERAMIC 0.1uF 50V 10% X7R 0402; Alt_Mfr_name: YAGEO AMERICA; Alt_Mfr_part_number: CC0402KRX5R8BB104; Chkd/date: MANIRAJA/261020; Crtd /date: ALVY/211020; Custom_Duty: 15%; Customs_HS_Code: 85322990; Distributor_name: DIGIKEY; Distributor_part_number: 490-10700-1-ND; Footprint Path: Y:\MIS_DATABASE\Library\ALTIUM_TOOL\PCB_FOOTPRINTS\Altium_Footprint_Lib.PcbLib; Height: 0.55MM; Library Path: Y:\MIS_DATABASE\Library\ALTIUM_TOOL\SCHEMATICS_PARTS\MS_DISCRETE_Library.schlib; Mfr_name: MURATA; Mfr_part_number: GRM155R71H104KE14D; Mistral Part No: 120011100014-R; Package: 0402; Part_type: CAPACITORS\CERAMIC; Project: J7_CP; RoHS: RoHS; Temperature: -55°C+125°C; Tolerance: 10%; Voltage: 50V; Wattage: NA; Weight: 3.1mg; Datasheet: Y:\MIS_DATABASE\DATASHEETS\CAPACITORS\GRM155R71H104KE14.PDF
R57 R66 = RESISTOR: RES 0E 1/20W 5% 0201; Chkd/date: NAVEED/301214; Crtd /date: MUDDU/120710; Custom_Duty: 15%; Customs_HS_Code: 85332119; Distributor_name: DIGIKEY; Distributor_part_number: 311-0.0NCT-ND; Footprint Path: Y:\MIS_DATABASE\Library\ALTIUM_TOOL\PCB_FOOTPRINTS\Altium_Footprint_Lib.PcbLib; Height: 0.26MM; Library Path: Y:\MIS_DATABASE\Library\ALTIUM_TOOL\SCHEMATICS_PARTS\MS_DISCRETE_Library.schlib; Mfr_name: YAGEO AMERICA; Mfr_part_number: RC0201JR-070RL; Mistral Part No: 110010070067-R; Package: 0201; Part_type: RESISTORS\FIXED; Project: PB_BUGBASE; RoHS: RoHS; SIGNAL_MODEL: RESISTOR_RES0201_0-5_0E_0E; Temperature: -55°C+125°C; Tolerance: 5%; Voltage: NA; Wattage: 1/20W; Weight: 0.17mg; Datasheet: Y:\MIS_DATABASE\DATASHEETS\RESISTORS\RCXXXXL-SER_MAR18.PDF
R89 = RESISTOR: RES 0E 1/20W 5% 0201; Chkd/date: NAVEED/301214; Crtd /date: MUDDU/120710; Custom_Duty: 15%; Customs_HS_Code: 85332119; Distributor_name: DIGIKEY; Distributor_part_number: 311-0.0NCT-ND; Footprint Path: Y:\MIS_DATABASE\Library\ALTIUM_TOOL\PCB_FOOTPRINTS\Altium_Footprint_Lib.PcbLib; Height: 0.26MM; Library Path: Y:\MIS_DATABASE\Library\ALTIUM_TOOL\SCHEMATICS_PARTS\MS_DISCRETE_Library.schlib; Mfr_name: YAGEO AMERICA; Mfr_part_number: RC0201JR-070RL; Mistral Part No: 110010070067-R; Package: 0201; Part_type: RESISTORS\FIXED; Project: PB_BUGBASE; RoHS: RoHS; SIGNAL_MODEL: RESISTOR_RES0201_0-5_22E_1%_22E_1%; Temperature: -55°C+125°C; Tolerance: 5%; Voltage: NA; Wattage: 1/20W; Weight: 0.17mg; Datasheet: Y:\MIS_DATABASE\DATASHEETS\RESISTORS\RCXXXXL-SER_MAR18.PDF
R364-R367 R376-R379 R396 = RESISTOR: RES 49.9K 1/20W 1% 0201; Chkd/date: MAZHAR/140108; Crtd /date: USMAN/140108; Cust_part_number: 4700-80185E; Custom_Duty: 15%; Customs_HS_Code: 85332119; Distributor_name: DIGIKEY; Distributor_part_number: P49.9KABCT-ND; Footprint Path: Y:\MIS_DATABASE\Library\ALTIUM_TOOL\PCB_FOOTPRINTS\Altium_Footprint_Lib.PcbLib; Height: 0.26MM; Library Path: Y:\MIS_DATABASE\Library\ALTIUM_TOOL\SCHEMATICS_PARTS\MS_DISCRETE_Library.schlib; Mfr_name: PANASONIC-ECG; Mfr_part_number: ERJ-1GEF4992C; Mistral Part No: 110009030900-R; Package: 0201; Part_type: RESISTORS\FIXED; Project: SD_WATERLOO; RoHS: RoHS; Temperature: -55°C+125°C; Tolerance: 1%; Voltage: NA; Wattage: 1/20W; Weight: 0.15mg; Datasheet: Y:\MIS_DATABASE\DATASHEETS\RESISTORS\PAN-ERJSER_NOV17.PDF
R399 R426 = RESISTOR: RES 49.9K 1/16W 1% 0402; Chkd/date: MAZHAR/220709; Crtd /date: GEETHA/090606; Custom_Duty: 15%; Customs_HS_Code: 85332119; Distributor_name: DIGIKEY; Distributor_part_number: 311-49.9KLRCT-ND; Footprint Path: Y:\MIS_DATABASE\Library\ALTIUM_TOOL\PCB_FOOTPRINTS\Altium_Footprint_Lib.PcbLib; Height: 0.40MM; Library Path: Y:\MIS_DATABASE\Library\ALTIUM_TOOL\SCHEMATICS_PARTS\MS_DISCRETE_Library.schlib; Mfr_name: YAGEO AMERICA; Mfr_part_number: RC0402FR-0749K9L; Mistral Part No: 110009030902-R; Package: 0402; Part_type: RESISTORS\FIXED; Project: PNAV; RoHS: RoHS; Temperature: -55°C+155°C; Tolerance: 1%; Voltage: NA; Wattage: 1/16W; Weight: 0.65mg; Datasheet: Y:\MIS_DATABASE\DATASHEETS\RESISTORS\RCXXXXL-SER_MAR18.PDF
U28 = MTFC16GAPALBH_TFBGA153: IC 32GB e-MMC MEMORY VFBGA153; Chkd/date: PRAVEEN/010922; Crtd /date: PRAVEEN/010922; Custom_Duty: 15%; Customs_HS_Code: 85423100; Distributor_name: DIGIKEY; Distributor_part_number: 557-MTFC32GAZAQHD-IT-ND; Footprint Path: Y:\MIS_DATABASE\Library\ALTIUM_TOOL\PCB_FOOTPRINTS\Altium_Footprint_Lib.PcbLib; Height: 0.90MM; Library Path: Y:\MIS_DATABASE\Library\ALTIUM_TOOL\SCHEMATICS_PARTS\MS_MISCMEMORY_Library.schlib; Mfr_name: MICRON; Mistral Part No: 141122090001-R; Package: VFBGA153; Part_type: ICS\DIGITAL\MEMORY; Project: J7AHP_SK_BRD; RoHS: RoHS; Temperature: -40°C+95°C; Tolerance: NA; Voltage: NA; Wattage: NA; Weight: NA; Datasheet: Y:\MIS_DATABASE\DATASHEETS\ICS\MEMORY\MTFC64GAZAQHD-IT.PDF
U58 = SN74LVC1G08DBVRE4_SOT23-5: IC SINGLE 2-INPUT POSITIVE AND GATE SOT23-5; Chkd/date: SUHAS/221010; Crtd /date: USMAN/151008; Custom_Duty: 15%; Customs_HS_Code: 85423100; Distributor_name: DIGIKEY; Distributor_part_number: SN74LVC1G08DBVRE4-ND; Height: 1.45MM; Mfr_name: TEXAS INSTRUMENTS; Mistral Part No: 141009060026-R; Part_type: ICS\DIGITAL\GATES; Project: KHAN_MAIN; RoHS: Sb/ Br FREE; Temperature: -40°C+85°C; Datasheet: Y:\MIS_DATABASE\DATASHEETS\ICS\DIGITAL\GATES\SN74LVC1G08.PDF
U12 = AM62-EVM_BGA425: IC AM62 SoC MICROPROCESSOR BGA425; Chkd/date: ALVY/110621; Crtd /date: MANIRAJA/110621; Custom_Duty: 15%; Customs_HS_Code: 85423100; Distributor_name: NA; Distributor_part_number: NA; Footprint Path: Y:\MIS_DATABASE\Library\ALTIUM_TOOL\PCB_FOOTPRINTS\Altium_Footprint_Lib.PcbLib; Height: 0.65MM; Library Path: Y:\MIS_DATABASE\Library\ALTIUM_TOOL\SCHEMATICS_PARTS\MS_MICROPROCESSOR_Library.schlib; Mfr_name: TEXAS INSTRUMENTS; Mistral Part No: 141221060001; Package: BGA425; Part_type: ICS\DIGITAL\MICROPROCESSOR; Project: AM62_EVM_BRD; RoHS: NA; Temperature: NA; Tolerance: NA; Voltage: NA; Wattage: NA; Weight: NA; Datasheet: Y:\MIS_DATABASE\DATASHEETS\ICS\DIGITAL\MICROCONTROLLER\AM62-SoC_SVB.PDF

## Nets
DGND: C3.2 C4.1 C5.2 C6.1 C7.1 C9.2 C10.1 C102.1 C328.1 C329.2 C330.2 C331.2 C333.2 C335.2 C336.2 C338.2 C339.2 C340.2 C341.2 C343.2 C344.2 C346.2 C347.2 C349.2 C350.2 C351.2 C352.1 C354.2 C358.2 C359.2 C362.1 C363.1 C380.2 J2.1(GND) J2.7(GND) J2.18(GND) J2.33(GND) J2.39(GND) J2.45(GND) J2.51(GND) J2.57(GND) J2.63(GND) J2.69(GND) J2.75(GND) J2.SH1 J2.SH2 R12.2 R98.2 R120.1 R122.1 R135.2 R272.2 R333.2 R393.2 R394.2 R398.2 R407.2 R671.1 R700.1 U1.2(GND) U2.7(GND) U2.15(TAB) U28.A6(VSS) U28.C4(VSSQ) U28.E7(VSS) U28.G5(VSS) U28.H10(VSS) U28.J5(VSS) U28.K8(VSS) U28.N2(VSSQ) U28.N5(VSSQ) U28.P4(VSSQ) U28.P6(VSSQ) U29.A2(VSSQ) U29.A8(VSSQ) U29.B2(VSS) U29.C9(VSSQ) U29.D2(VSSQ) U29.D8(VSSQ) U29.E1(VSS) U29.E3(VSSQ) U29.E8(VSSQ) U29.E9(VSS) U29.F1(VSSQ) U29.G8(VSS) U29.H1(VSSQ) U29.H9(VSSQ) U29.K1(VSS) U29.K9(VSS) U29.M9(VSS) U29.N1(VSS) U29.T1(VSS) U58.3(GND) ; also on sheet 1 10 11 12 13 14 15 16 20 21 22 23 24 25 26 27 28 29 30 31 32 33 34 35 36 37 38 39 40 41 42 43
VCC_1V8: C7.2 C333.1 C341.1 C380.1 R4.1 R6.2 R10.2 R18.2 R19.2 R20.2 R21.2 R22.2 R364.1 R365.1 R366.1 R367.1 R376.1 R377.1 R378.1 R379.1 R396.1 R399.1 R426.1 R703.2 U2.1(VCCA) U28.C6(VCCQ) U28.M4(VCCQ) U28.N4(VCCQ) U28.P3(VCCQ) U28.P5(VCCQ) U58.5(VCC) ; also on sheet 12 13 14 21 25 34 37 39 40 42
VCC_3V3_SYS: C3.1 C4.2 C6.2 C9.1 C10.2 C335.1 C338.1 J2.2(3-3V) J2.4(3-3V) J2.72(3-3V) J2.74(3-3V) R3.1 R273.2 R427.2 R701.2 R704.2 R715.2 U2.14(VCCB) U28.E6(VCC) U28.F5(VCC) U28.J10(VCC) U28.K9(VCC) ; also on sheet 10 12 13 14 20 22 23 24 25 26 27 29 30 31 32 33 34 35 36 37 38 39 40 41 42 43
VDD_2V5: FL23.1 ; also on sheet 13 23 24
VDD_DDR4: C329.1 C336.1 C337.2 C339.1 C340.1 C343.1 C344.1 C346.1 C347.1 C349.1 C350.1 C354.1 C358.1 C359.1 C361.2 R118.2 R119.2 R121.2 R408.1 U29.A1(VDDQ) U29.A9(VDDQ) U29.B3(VDD) U29.B9(VDD) U29.C1(VDDQ) U29.D1(VDD) U29.D9(VDDQ) U29.F2(VDDQ) U29.F8(VDDQ) U29.G1(VDDQ) U29.G7(VDD) U29.G9(VDDQ) U29.J1(VDD) U29.J2(VDDQ) U29.J8(VDDQ) U29.J9(VDD) U29.L1(VDD) U29.L9(VDD) U29.R1(VDD) U29.T9(VDD) ; also on sheet 14 15 16
VDDIM: C330.1 C331.1 U28.C2(VDDIM)
BT_EN_SOC_3V3: J2.54(W_DISABLE2#) R273.1 ; also on sheet 34
BT_UART_WAKE_1V8: R2.2 U2.4(A3)
BT_UART_WAKE_CONN: J2.20(UART_WAKE#) R1.1 R2.1
BT_UART_WAKE_SOC_3V3: R1.2 R704.1 U2.11(B3) ; also on sheet 39
BT_WLAN_EN: J2.56(W_DISABLE1#) R23.2 R272.1 R702.2
DDR_A0: U12.J1(DDR0_A0) U29.P3(A0)
DDR_A1: U12.J2(DDR0_A1) U29.P7(A1)
DDR_A2: U12.K3(DDR0_A2) U29.R3(A2)
DDR_A3: U12.L5(DDR0_A3) U29.N7(A3)
DDR_A4: U12.K4(DDR0_A4) U29.N3(A4)
DDR_A5: U12.K1(DDR0_A5) U29.P8(A5)
DDR_A6: U12.R2(DDR0_A6) U29.P2(A6)
DDR_A7: U12.P2(DDR0_A7) U29.R8(A7)
DDR_A8: U12.P1(DDR0_A8) U29.R2(A8)
DDR_A9: U12.P4(DDR0_A9) U29.R7(A9)
DDR_A10: U12.R5(DDR0_A10) U29.M3(A10/AP)
DDR_A11: U12.P5(DDR0_A11) U29.T2(A11)
DDR_A12: U12.R6(DDR0_A12) U29.M7(A12/BC_N)
DDR_A13: U12.R1(DDR0_A13) U29.T8(A13)
DDR_A14_WEn: U12.N3(DDR0_WE_N) U29.L2(WE_N/A14)
DDR_A15_CAS: U12.M4(DDR0_CAS_N) U29.M8(CAS_N/A15)
DDR_A16_RAS: U12.M5(DDR0_RAS_N) U29.L8(RAS_N/A16)
DDR_ACTn: U12.N6(DDR0_ACT_N) U29.L3(ACT_N)
DDR_ALERTn: R118.1 U12.R3(DDR0_ALERT_N) U29.P9(ALERT_N)
DDR_BA0: U12.M1(DDR0_BA0) U29.N2(BA0)
DDR_BA1: U12.N1(DDR0_BA1) U29.N8(BA1)
DDR_BG0: U12.T4(DDR0_BG0) U29.M2(BG0)
DDR_CKE: R394.1 U12.H2(DDR0_CKE0) U29.K2(CKE)
DDR_CLKN: R395.1 U12.L2(DDR0_CK0_N) U29.K8(CK_C)
DDR_CLKP: R397.1 U12.L1(DDR0_CK0) U29.K7(CK_T)
DDR_CSn: U12.L6(DDR0_CS0_N) U29.L7(CS_N)
DDR_DQ0: U12.F4(DDR0_DQ0) U29.G2(DQ0)
DDR_DQ1: U12.H6(DDR0_DQ3) U29.F7(DQ1)
DDR_DQ2: U12.E3(DDR0_DQ4) U29.H3(DQ2)
DDR_DQ3: U12.F3(DDR0_DQ2) U29.H7(DQ3)
DDR_DQ4: U12.F1(DDR0_DQ7) U29.H2(DQ4)
DDR_DQ5: U12.G5(DDR0_DQ1) U29.H8(DQ5)
DDR_DQ6: U12.G2(DDR0_DQ5) U29.J3(DQ6)
DDR_DQ7: U12.F2(DDR0_DQ6) U29.J7(DQ7)
DDR_DQ8: U12.U1(DDR0_DQ8) U29.A3(DQ8)
DDR_DQ9: U12.U3(DDR0_DQ9) U29.B8(DQ9)
DDR_DQ10: U12.U2(DDR0_DQ10) U29.C3(DQ10)
DDR_DQ11: U12.V5(DDR0_DQ11) U29.C7(DQ11)
DDR_DQ12: U12.W2(DDR0_DQ12) U29.C2(DQ12)
DDR_DQ13: U12.V6(DDR0_DQ13) U29.C8(DQ13)
DDR_DQ14: U12.Y1(DDR0_DQ14) U29.D3(DQ14)
DDR_DQ15: U12.W1(DDR0_DQ15) U29.D7(DQ15)
DDR_LDM: U12.H5(DDR0_DM0) U29.E7(NF/LDM_N/LDBI_N)
DDR_LDQS_N: U12.E2(DDR0_DQS0_N) U29.F3(LDQS_C)
DDR_LDQS_P: U12.E1(DDR0_DQS0) U29.G3(LDQS_T)
DDR_ODT: U12.H1(DDR0_ODT0) U29.K3(ODT)
DDR_PARITY: U12.T1(DDR0_PAR) U29.T3(PAR)
DDR_RESET#: R119.1 R120.2 U12.G1(DDR0_RESET0_N) U29.P1(RESET_N)
DDR_TEN: R121.1 R122.2 U29.N9(TEN)
DDR_UDM: U12.W5(DDR0_DM1) U29.E2(NF/UDM_N/UDBI_N)
DDR_UDQS_N: U12.V2(DDR0_DQS1_N) U29.A7(UDQS_C)
DDR_UDQS_P: U12.V1(DDR0_DQS1) U29.B7(UDQS_T)
DDR_VPP: C328.2 C351.1 C352.2 FL23.2 U29.B1(VPP) U29.R9(VPP)
DDR_VREFCA: C102.2 C361.1 C362.2 C363.2 R407.1 R408.2 TP43.1(TP) U29.M1(VREFCA)
eMMC_RSTn: R426.2 U28.K5(RST_N) U58.4(Y)
GPIO_eMMC_RSTn: R427.1 U58.1(A) ; also on sheet 39
HFOSC0_CLKOUT_32K: R7.1 ; also on sheet 32
M2_LED1#: J2.6(LED_1#) TP3.1(TP)
M2_LED2#: J2.16(LED_2#) TP4.1(TP)
MCASP1_ACLKX_BT_1V8: J2.8(PCM_CLK/I2S_SCK) ; also on sheet 39
MCASP1_AFSX_BT_1V8: J2.10(PCM_SYNC/I2S_WS) ; also on sheet 39
MCASP1_AXR0_BT_1V8: J2.12(PCM_IN/I2S_SD_IN) R671.2 ; also on sheet 39
MCASP1_AXR2_BT_1V8: J2.14(PCM_OUT/I2S_SD_OUT) ; also on sheet 39
MMC0_CLK: R89.1 R398.1 R399.2 U28.M6(CLK)
MMC1_CLK: R66.1 R333.1 ; also on sheet 20
MMC1_CLK_R: R66.2 U12.B22(MMC1_CLK)
MMC1_CMD: U12.A21(MMC1_CMD) ; also on sheet 20
MMC1_D0: U12.A22(MMC1_DAT0) ; also on sheet 20
MMC1_D1: U12.B21(MMC1_DAT1) ; also on sheet 20
MMC1_D2: U12.C21(MMC1_DAT2) ; also on sheet 20
MMC1_D3: U12.D22(MMC1_DAT3) ; also on sheet 20
MMC1_SDCD: U12.D17(MMC1_SDCD) ; also on sheet 20
MMC2_CLK: R8.2 R12.1 R57.2
MMC2_CLK_COM: J2.9(SDIO_CLK/SYSCLK) R8.1 R10.1
MMC2_CMD: R282.2 U12.C24(MMC2_CMD)
MMC2_CMD_COM: J2.11(SDIO_CMD) R20.1 R282.1
MMC2_D0: R284.2 U12.B24(MMC2_DAT0)
MMC2_D0_COM: J2.13(SDIO_DATA0) R18.1 R284.1
MMC2_D1: R283.2 U12.C25(MMC2_DAT1)
MMC2_D1_COM: J2.15(SDIO_DATA1) R19.1 R283.1
MMC2_D2: R281.2 U12.E23(MMC2_DAT2)
MMC2_D2_COM: J2.17(SDIO_DATA2) R21.1 R281.1
MMC2_D3: R280.2 U12.D24(MMC2_DAT3)
MMC2_D3_COM: J2.19(SDIO_DATA3) R22.1 R280.1
RESETSTATz: U58.2(B) ; also on sheet 13 20 21 23 24 27 32 33 37 39 40 41 42
SLOW_CLK: J2.50(SUSCLK_32kHz) R5.2 R7.2
SOC_GPIO1_49: U12.C17(MMC1_SDWP) ; also on sheet 38
SOC_MMC0_CLK: R89.2 U12.AB1(MMC0_CLK)
SOC_MMC0_CMD: R396.2 U12.Y3(MMC0_CMD) U28.M5(CMD)
SOC_MMC0_DAT0: R378.2 U12.AA2(MMC0_DAT0) U28.A3(DAT0)
SOC_MMC0_DAT1: R377.2 U12.AA1(MMC0_DAT1) U28.A4(DAT1)
SOC_MMC0_DAT2: R376.2 U12.AA3(MMC0_DAT2) U28.A5(DAT2)
SOC_MMC0_DAT3: R379.2 U12.Y4(MMC0_DAT3) U28.B2(DAT3)
SOC_MMC0_DAT4: R367.2 U12.AB2(MMC0_DAT4) U28.B3(DAT4)
SOC_MMC0_DAT5: R366.2 U12.AC1(MMC0_DAT5) U28.B4(DAT5)
SOC_MMC0_DAT6: R365.2 U12.AD2(MMC0_DAT6) U28.B5(DAT6)
SOC_MMC0_DAT7: R364.2 U12.AC2(MMC0_DAT7) U28.B6(DAT7)
SoC_MMC2_CLK: R57.1 U12.D25(MMC2_CLK)
SOC_UART1_CTS_BT_1V8: J2.34(UART_CTS) ; also on sheet 37
SOC_UART1_RTS_BT_1V8: J2.36(UART_RTS) ; also on sheet 37
SOC_UART1_RX_BT_1V8: J2.22(UART_RXD) ; also on sheet 37
SOC_UART1_TX_BT_1V8: R24.2 ; also on sheet 37
SoC_WLAN_EN_1V8: R23.1 U2.3(A2) U12.A23(MMC2_SDCD)
SoC_WLAN_EN_3V3: R702.1 U2.12(B2)
SoC_WLAN_IRQ_1V8: J2.21(SDIO_WAKE#) R6.1 U12.B23(MMC2_SDWP)
USB_DM: J2.5(USB_D-) TP2.1(TP)
USB_DP: J2.3(USB_D+) TP1.1(TP)
WL_LT_EN: R700.2 R701.1 U2.8(OE) ; also on sheet 39
WLAN_ALERT_1V8: R11.2 U2.5(A4)
WLAN_ALERT_3V3: R715.1 U2.10(B4) ; also on sheet 39
WLAN_SDIO_RST_1V8: J2.23(SDIO_RESET#/TX_BLANKING) R703.1 U2.2(A1)
WLAN_SDIO_RST_3V3: U2.13(B1) ; also on sheet 39
N15835426: R135.1 U29.F9(ZQ)
N15835430: TP35.1(TP) U29.T7(NF/NC)
N15951745: C5.1 R3.2 R4.2 U1.1(TRI-STATE) U1.4(VDD)
N15952254: R5.1 U1.3(OUTPUT)
N16878497: R393.1 TP90.1(TP) U28.H5(DS)
N16887346: R98.1 U12.M2(DDR0_CAL0)
N17010152: C337.1 R395.2 R397.2
N20600664: J2.32(UART_TXD) R24.1
N20605838: J2.62(ALERT#) R11.1

Not connected (* = marked no-connect by the designer): J2 35(PETP0)* 37(PETN0)* 38(VENDOR_DEFINED1)* 40(VENDOR_DEFINED2)* 41(PERP0)* 42(VENDOR_DEFINED3)* 43(PERN0)* 44(COEX3)* 46(COEX_RXD)* 47(REFCLKP0)* 48(COEX_TXD)* 49(REFCLKN0)* 52(PERST0#)* 53(CLKREQ0#)* 55(PEWAKE0#)* 58(I2C_DATA)* 59(RESERVED/PETP1)* 60(I2C_CLK)* 61(RESERVED/PETN1)* 64(RESERVED)* 65(RESERVED/PERP1)* 66(UIM_SWP/PERST1#)* 67(RESERVED/PERN1)* 68(UIM_POWER_SNK/CLKREQ1#)* 70(UIM_POWER_SRC/GPIO1/PEWAKE#)* 71(RESERVED/REFCLKP1)* 73(RESERVED/REFCLKN1)* SH3*; U2 6(NC1)* 9(NC2)*; U12 J3(DDR0_ODT1)* J4(DDR0_CKE1)* K2(DDR0_CS1_N)* N2(DDR0_BG1)* T2(RSVD4)* U4(RSVD5)*; U28 A1(NC1)* A2(NC2)* A7(RFU1)* A8(NC3)* A9(NC4)* A10(NC5)* A11(NC6)* A12(NC7)* A13(NC8)* A14(NC9)* B1(NC10)* B7(NC11)* B8(NC12)* B9(NC13)* B10(NC14)* B11(NC15)* B12(NC16)* B13(NC17)* B14(NC18)* C1(NC19)* C3(NC20)* C5(NC21)* C7(NC22)* C8(NC23)* C9(NC24)* C10(NC25)* C11(NC26)* C12(NC27)* C13(NC28)* C14(NC29)* D1(NC30)* D2(NC31)* D3(NC32)* D4(NC33)* D12(NC34)* D13(NC35)* D14(NC36)* E1(NC37)* E2(NC38)* E3(NC39)* E5(RFU2)* E8(VSF1)* E9(VSF2)* E10(VSF3)* E12(NC40)* E13(NC41)* E14(NC42)* F1(NC43)* F2(NC44)* F3(NC45)* F10(VSF4)* F12(NC46)* F13(NC47)* F14(NC48)* G1(NC49)* G2(NC50)* G3(NC51)* G10(VSF5)* G12(NC52)* G13(NC53)* G14(NC54)* H1(NC55)* H2(NC56)* H3(NC57)* H12(NC58)* H13(NC59)* H14(NC60)* J1(NC61)* J2(NC62)* J3(NC63)* J12(NC64)* J13(NC65)* J14(NC66)* K1(NC67)* K2(NC68)* K3(NC69)* K6(RFU3)* K7(RFU4)* K10(VSF6)* K12(NC70)* K13(NC71)* K14(NC72)* L1(NC73)* L2(NC74)* L3(NC75)* L12(NC76)* L13(NC77)* L14(NC78)* M1(NC79)* M2(NC80)* M3(NC81)* M7(NC82)* M8(NC83)* M9(NC84)* M10(NC85)* M11(NC86)* M12(NC87)* M13(NC88)* M14(NC89)* N1(NC90)* N3(NC91)* N6(NC92)* N7(NC93)* N8(NC94)* N9(NC95)* N10(NC96)* N11(NC97)* N12(NC98)* N13(NC99)* N14(NC100)* P1(NC101)* P2(NC102)* P7(NC103)* P8(NC104)* P9(NC105)* P10(VSF7)* P11(NC106)* P12(NC107)* P13(NC108)* P14(NC109)*

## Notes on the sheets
sheet 17
- SOC DDR4 INTERFACE
- D-NOTE: DDR DQ Lines Swapped
  Within Data Byte
- R-Note :-
  Verify need to connect DDR0_BG1
  for memory expansion
- Reserved Pins,
  Leave Unconnected
- R-Note :-
  Verify need to connect these NC pins
  for memory expansion
- R-Note :-
  Pulldown is populated
- DDR4 DEVICE
- D-Note :-
  Refer TMDS64EVM for implementing VTT
  terminations for DDR4 address and control
  signals when a single DDR device is used
- Cad Note:
  Place one of the decap near
  to DDR_VREFCA
- R-Note :-
  Pulldown is populated
- R-Note :-
  Pulldown is DNI
sheet 18
- M.2 INTERFACE
- 1.8V
- 1.8V
- CAD NOTE: PLACE TERMINATION RESISTORS CLOSER TO SoC
- SoC_MAIN_UART1_RXD
- SoC_MAIN_UART1_TXD
- SoC_MAIN_UART1_CTS
- 1.8V
- SoC_MAIN_UART1_RTS
- D-Note :-
  Add a bulk cap when oscillator is used
- CAD Note:-
  Place R5 & R7 close
  to each other to
  avoid stub.
- D-Note :-
  Ok to use 10K, 5%
- WL_LT_EN = Active High
sheet 19
- SOC - MMC Interface
- D-Note :-
  0E provision on MMC0_CLK
  Helps improve signal integrity
- eMMC FLASH
- D-Note :-
  MMC0 interface is compliant
  with the JEDEC eMMC electrical
  standard v5.1 (JESD84-B51)
- D-Note :-
  For D7..D1 eMMC device is expected to have the
  pullups enabled by default.
  The eMMC host/phy disables the eMMC device pullups
  and enables SOC internal pullups.
  Provision for external pullups is optional or the
  pullups can be deleted.
- D-Note :-
  Add additional decaps as required
  Refer SK-AM62P-LP schematics
- D-Note :-
  This family of processor implements a soft PHY
  for eMMC interface.
  The pulls required for D0, Clock and other
  eMMC interface control signals are recommended
  to be implemented externally
- CAD Note :-
  Place SOC clock output pulldown
  resistor near to the clock input pin
  of the attached (memory) device
- D-Note :-
  Ok to use standard 47K
  or similar resistor for
  all the parallel pulls
- GPIO1_49
- R-Note :-
  What is the reason we selected
  pulldown instead of pullup for EMMC,
  SD card or other peripherals?
  Because there are cases where the
  clock is stopped or paused in a low
  logic state and the pull-down option
  is consistent with this logic state.
- 1.8V
- eMMC FLASH RESET
- D-Note :-
  Ensure eMMC_RSTn Reset input
  is enabled in the eMMC
  device (eMMC non-volatile
  configuration space) for the
  reset logic to be functional
- D-Note :-
  Add a series resistor to the GPIO
  input for isolation or testing
  Refer SK-AM62P-LP schematics
- D-Note :-
  The GPIO reset option makes it possible for
  software to reset the attached device (eMMC or
  OSPI or SD card or OLDI or EPHY) without
  resetting the entire processor if there is a
  case where the peripheral becomes unresponsive.
- D-Note :-
  Ok to use standard 47K or similar
  resistor for all the parallel pulls
- D-Note :-
  You could eliminate the GPIO option and only use
  the reset output (Warm or Cold), where software
  forces a warm reset if the peripheral becomes
  unresponsive. However, this will reset the
  entire device rather than trying to recover the
  specific peripheral without resetting the entire
  device.
- D-Note :-
  In case ANDing logic is not used and the
  processor Main Domain warm reset status output
  (RESETSTATz) is used to reset the attached
  device, ensure the IO voltage level of the
  attached device matches the RESETSTATz IO
  voltage level. A level translator is
  recommended to match the IO voltage level.A
  resistor divider could be used alternatively,
  provided optimum impedance value of the
  resistor divider is selected.If too high the
  rise/fall time of the eMMC reset input could be
  slow and introduce too much delay. If too low
  it will cause the AM62x to source too much
  steady-state current during normal operation.
- D-Note :-
  ANDing logic additionally performs level translation
  Verify the Reset IO level compatibility before
  optimizing the reset ANDing logic.
  IO level mismatch could cause supply leakage and
  affect SOC operation
